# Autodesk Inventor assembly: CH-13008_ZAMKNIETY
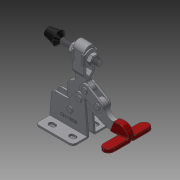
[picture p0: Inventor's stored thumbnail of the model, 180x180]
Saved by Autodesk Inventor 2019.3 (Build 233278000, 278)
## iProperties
Company: Î¢ÈíÖÐ¹ú
Created: 2012-09
Part Number: CH-13008_ZAMKNIETY
Material: Ogólny
Description: STEP AP203
Document SubType Name: Assembly
Designer: CADENGINEERING4
Stock Number: DOCISK PIONOWY
Sending System: SolidWorks 2010
Preprocessor: SwSTEP 2.0
Title: CH-13008.STEP
Author: Î¢ÈíÓÃ»§
Revision Number: ÈÎºÎ
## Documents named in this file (10)
- D:\Vault_2016\Projekty\Clamptek\STRONA\Vertical toggle clamp\CH-13008\CH-13008_OTWARTY.iam
- D:\Vault_2016\Projekty\Clamptek\STRONA\Vertical toggle clamp\CH-13008\CH-13008-05.ipt
- D:\Vault_2016\Projekty\Clamptek\STRONA\Vertical toggle clamp\CH-13008\CH-13008-03 T-HANDLE.ipt
- D:\Vault_2016\Projekty\Clamptek\STRONA\Vertical toggle clamp\CH-13008\CH-13008-02 U-BAR.ipt
- D:\Vault_2016\Projekty\Clamptek\STRONA\Vertical toggle clamp\CH-13008\CH-13008-06.ipt
- D:\Vault_2016\Projekty\Clamptek\STRONA\Vertical toggle clamp\CH-13008\CH-13008-01 FLANGED BASE.ipt
- D:\Vault_2016\Projekty\Clamptek\STRONA\Vertical toggle clamp\CH-13008\CH-FC-38312 Nut.ipt
- D:\Vault_2016\Projekty\Clamptek\STRONA\Vertical toggle clamp\CH-13008\CH-13008-04 CONNECTING-PIATE.ipt
- D:\Vault_2016\Projekty\Clamptek\STRONA\Vertical toggle clamp\CH-13008\CH-FC-38312 SPINDLE SUPPLIED.ipt
- D:\Vault_2016\Projekty\Clamptek\STRONA\Vertical toggle clamp\CH-13008\CH-FW-380.ipt
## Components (18 placed, 18 different names)
1. CH-13008-05_1 — Zestawiające:2
2. CH-13008-03 T-HANDLE_2 — Zestawiające:5, Zestawiające:6, Zestawiające:7, Zestawiające:16, Zestawiające:20, Zestawiające:37
3. CH-13008-02 U-BAR_3 — Zestawiające:22, Zestawiające:24, Zestawiające:25, Zestawiające:26, Zestawiające:27, Zestawiające:35, Zestawiające:37, Kątowe:1, Kątowe:2, Zestawiające:38
4. CH-13008-05_4 — Zestawiające:3, Zestawiające:17, Zestawiające:19
5. CH-13008-06_5 — Zestawiające:12, Zestawiające:15
6. CH-13008-01 FLANGED BASE_6 — Zestawiające:1, Zestawiające:2, Zestawiające:5, Zestawiające:12, Zestawiające:13, Zestawiające:14, Zestawiające:15, Zestawiające:24
7. CH-FC-38312 Nut_7 — Zestawiające:30, Zestawiające:31, Zestawiające:36
8. CH-13008-04 CONNECTING-PIATE_8 — Zestawiające:6, Zestawiające:8, Zestawiające:9, Zestawiające:10, Zestawiające:11, Zestawiające:18, Zestawiające:20
9. CH-13008-06_9 — Zestawiające:9, Zestawiające:10
10. CH-13008-04 CONNECTING-PIATE_10 — Zestawiające:3, Zestawiające:4, Zestawiające:7, Zestawiające:17, Zestawiające:18, Zestawiające:19, Zestawiające:21, Zestawiające:23, Zestawiające:35
11. CH-FC-38312 SPINDLE SUPPLIED_11 — Zestawiające:36, Równoległe:1
12. CH-13008-05_12 — Zestawiające:1
13. CH-FC-38312 Nut_13 — Zestawiające:32, Zestawiające:33
14. CH-FW-380_14 — Zestawiające:25, Zestawiające:28, Zestawiające:32, Zestawiające:33, Równoległe:1, Kątowe:2
15. CH-13008-05_15 — Zestawiające:4, Zestawiające:21
16. CH-13008-06_16 — Zestawiające:8, Zestawiające:11, Zestawiające:22, Zestawiające:23
17. CH-13008-06_17 — Zestawiające:13, Zestawiające:14, Zestawiające:16
18. CH-FW-380_18 — Zestawiające:26, Zestawiające:27, Zestawiające:28, Zestawiające:30, Zestawiające:31, Kątowe:1, Zestawiające:38
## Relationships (39: Mate 36, Angle 2, Flush 1)
- Zestawiające:1 [Mate]: CH-13008-01 FLANGED BASE_6 ↔ CH-13008-05_12
- Zestawiające:2 [Mate]: CH-13008-05_1 ↔ CH-13008-01 FLANGED BASE_6
- Zestawiające:3 [Mate]: CH-13008-05_4 ↔ CH-13008-04 CONNECTING-PIATE_10
- Zestawiające:4 [Mate]: CH-13008-04 CONNECTING-PIATE_10 ↔ CH-13008-05_15
- Zestawiające:5 [Mate]: CH-13008-03 T-HANDLE_2 ↔ CH-13008-01 FLANGED BASE_6
- Zestawiające:6 [Mate]: CH-13008-03 T-HANDLE_2 ↔ CH-13008-04 CONNECTING-PIATE_8
- Zestawiające:7 [Mate]: CH-13008-03 T-HANDLE_2 ↔ CH-13008-04 CONNECTING-PIATE_10
- Zestawiające:8 [Mate]: CH-13008-04 CONNECTING-PIATE_8 ↔ CH-13008-06_16
- Zestawiające:9 [Mate]: CH-13008-04 CONNECTING-PIATE_8 ↔ CH-13008-06_9
- Zestawiające:10 [Mate]: CH-13008-04 CONNECTING-PIATE_8 ↔ CH-13008-06_9
- Zestawiające:11 [Mate]: CH-13008-04 CONNECTING-PIATE_8 ↔ CH-13008-06_16
- Zestawiające:12 [Mate]: CH-13008-06_5 ↔ CH-13008-01 FLANGED BASE_6
- Zestawiające:13 [Mate]: CH-13008-01 FLANGED BASE_6 ↔ CH-13008-06_17
- Zestawiające:14 [Mate]: CH-13008-01 FLANGED BASE_6 ↔ CH-13008-06_17
- Zestawiające:15 [Mate]: CH-13008-06_5 ↔ CH-13008-01 FLANGED BASE_6
- Zestawiające:16 [Mate]: CH-13008-03 T-HANDLE_2 ↔ CH-13008-06_17
- Zestawiające:17 [Mate]: CH-13008-05_4 ↔ CH-13008-04 CONNECTING-PIATE_10
- Zestawiające:18 [Mate]: CH-13008-04 CONNECTING-PIATE_8 ↔ CH-13008-04 CONNECTING-PIATE_10
- Zestawiające:19 [Mate]: CH-13008-05_4 ↔ CH-13008-04 CONNECTING-PIATE_10
- Zestawiające:20 [Mate]: CH-13008-03 T-HANDLE_2 ↔ CH-13008-04 CONNECTING-PIATE_8
- Zestawiające:21 [Mate]: CH-13008-04 CONNECTING-PIATE_10 ↔ CH-13008-05_15
- Zestawiające:22 [Mate]: CH-13008-02 U-BAR_3 ↔ CH-13008-06_16
- Zestawiające:23 [Mate]: CH-13008-04 CONNECTING-PIATE_10 ↔ CH-13008-06_16
- Zestawiające:24 [Mate]: CH-13008-02 U-BAR_3 ↔ CH-13008-01 FLANGED BASE_6
- Zestawiające:25 [Mate]: CH-13008-02 U-BAR_3 ↔ CH-FW-380_14
- Zestawiające:26 [Mate]: CH-13008-02 U-BAR_3 ↔ CH-FW-380_18
- Zestawiające:27 [Mate]: CH-13008-02 U-BAR_3 ↔ CH-FW-380_18
- Zestawiające:28 [Mate]: CH-FW-380_14 ↔ CH-FW-380_18
- Zestawiające:30 [Mate]: CH-FC-38312 Nut_7 ↔ CH-FW-380_18
- Zestawiające:31 [Mate]: CH-FC-38312 Nut_7 ↔ CH-FW-380_18
- Zestawiające:32 [Mate]: CH-FC-38312 Nut_13 ↔ CH-FW-380_14
- Zestawiające:33 [Mate]: CH-FC-38312 Nut_13 ↔ CH-FW-380_14
- Zestawiające:35 [Mate]: CH-13008-02 U-BAR_3 ↔ CH-13008-04 CONNECTING-PIATE_10
- Zestawiające:36 [Mate]: CH-FC-38312 Nut_7 ↔ CH-FC-38312 SPINDLE SUPPLIED_11
- Równoległe:1 [Flush]: CH-FC-38312 SPINDLE SUPPLIED_11 ↔ CH-FW-380_14
- Zestawiające:37 [Mate]: CH-13008-03 T-HANDLE_2 ↔ CH-13008-02 U-BAR_3
- Kątowe:1 [Angle]: CH-13008-02 U-BAR_3 ↔ CH-FW-380_18
- Kątowe:2 [Angle]: CH-13008-02 U-BAR_3 ↔ CH-FW-380_14
- Zestawiające:38 [Mate]: CH-13008-02 U-BAR_3 ↔ CH-FW-380_18
